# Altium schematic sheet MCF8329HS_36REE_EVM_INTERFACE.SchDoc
size 431 x 279 mm; Date: Not shown in title block; ApprovedBy: Not shown in title block; CheckedBy: Not shown in title block; Author: Not shown in title block; CompanyName: Not shown in title block; Engineer: Not shown in title block; Organization: Not shown in title block; Address1: Not shown in title block; Address2: Not shown in title block; Address3: Not shown in title block; Address4: Not shown in title block; DocumentNumber: 1; Revision: Use project parameter SCH_Rev; SheetNumber: 1; SheetTotal: 5; PageSetup: Record=PageOptions¦CenterHorizontal=True¦CenterVertical=True¦PrintScale=1.00¦XCorrection=1.00¦YCorrection=1.00¦PrintKind=0¦BorderSize=5000000¦LeftOffset=0¦BottomOffset=0¦Orientation=2¦PaperLength=1000¦PaperWidth=1000¦Scale=100¦PaperSource=15¦PrintQuality=600¦MediaType=1¦DitherType=10¦PaperKind=Letter¦PrintScaleMode=1
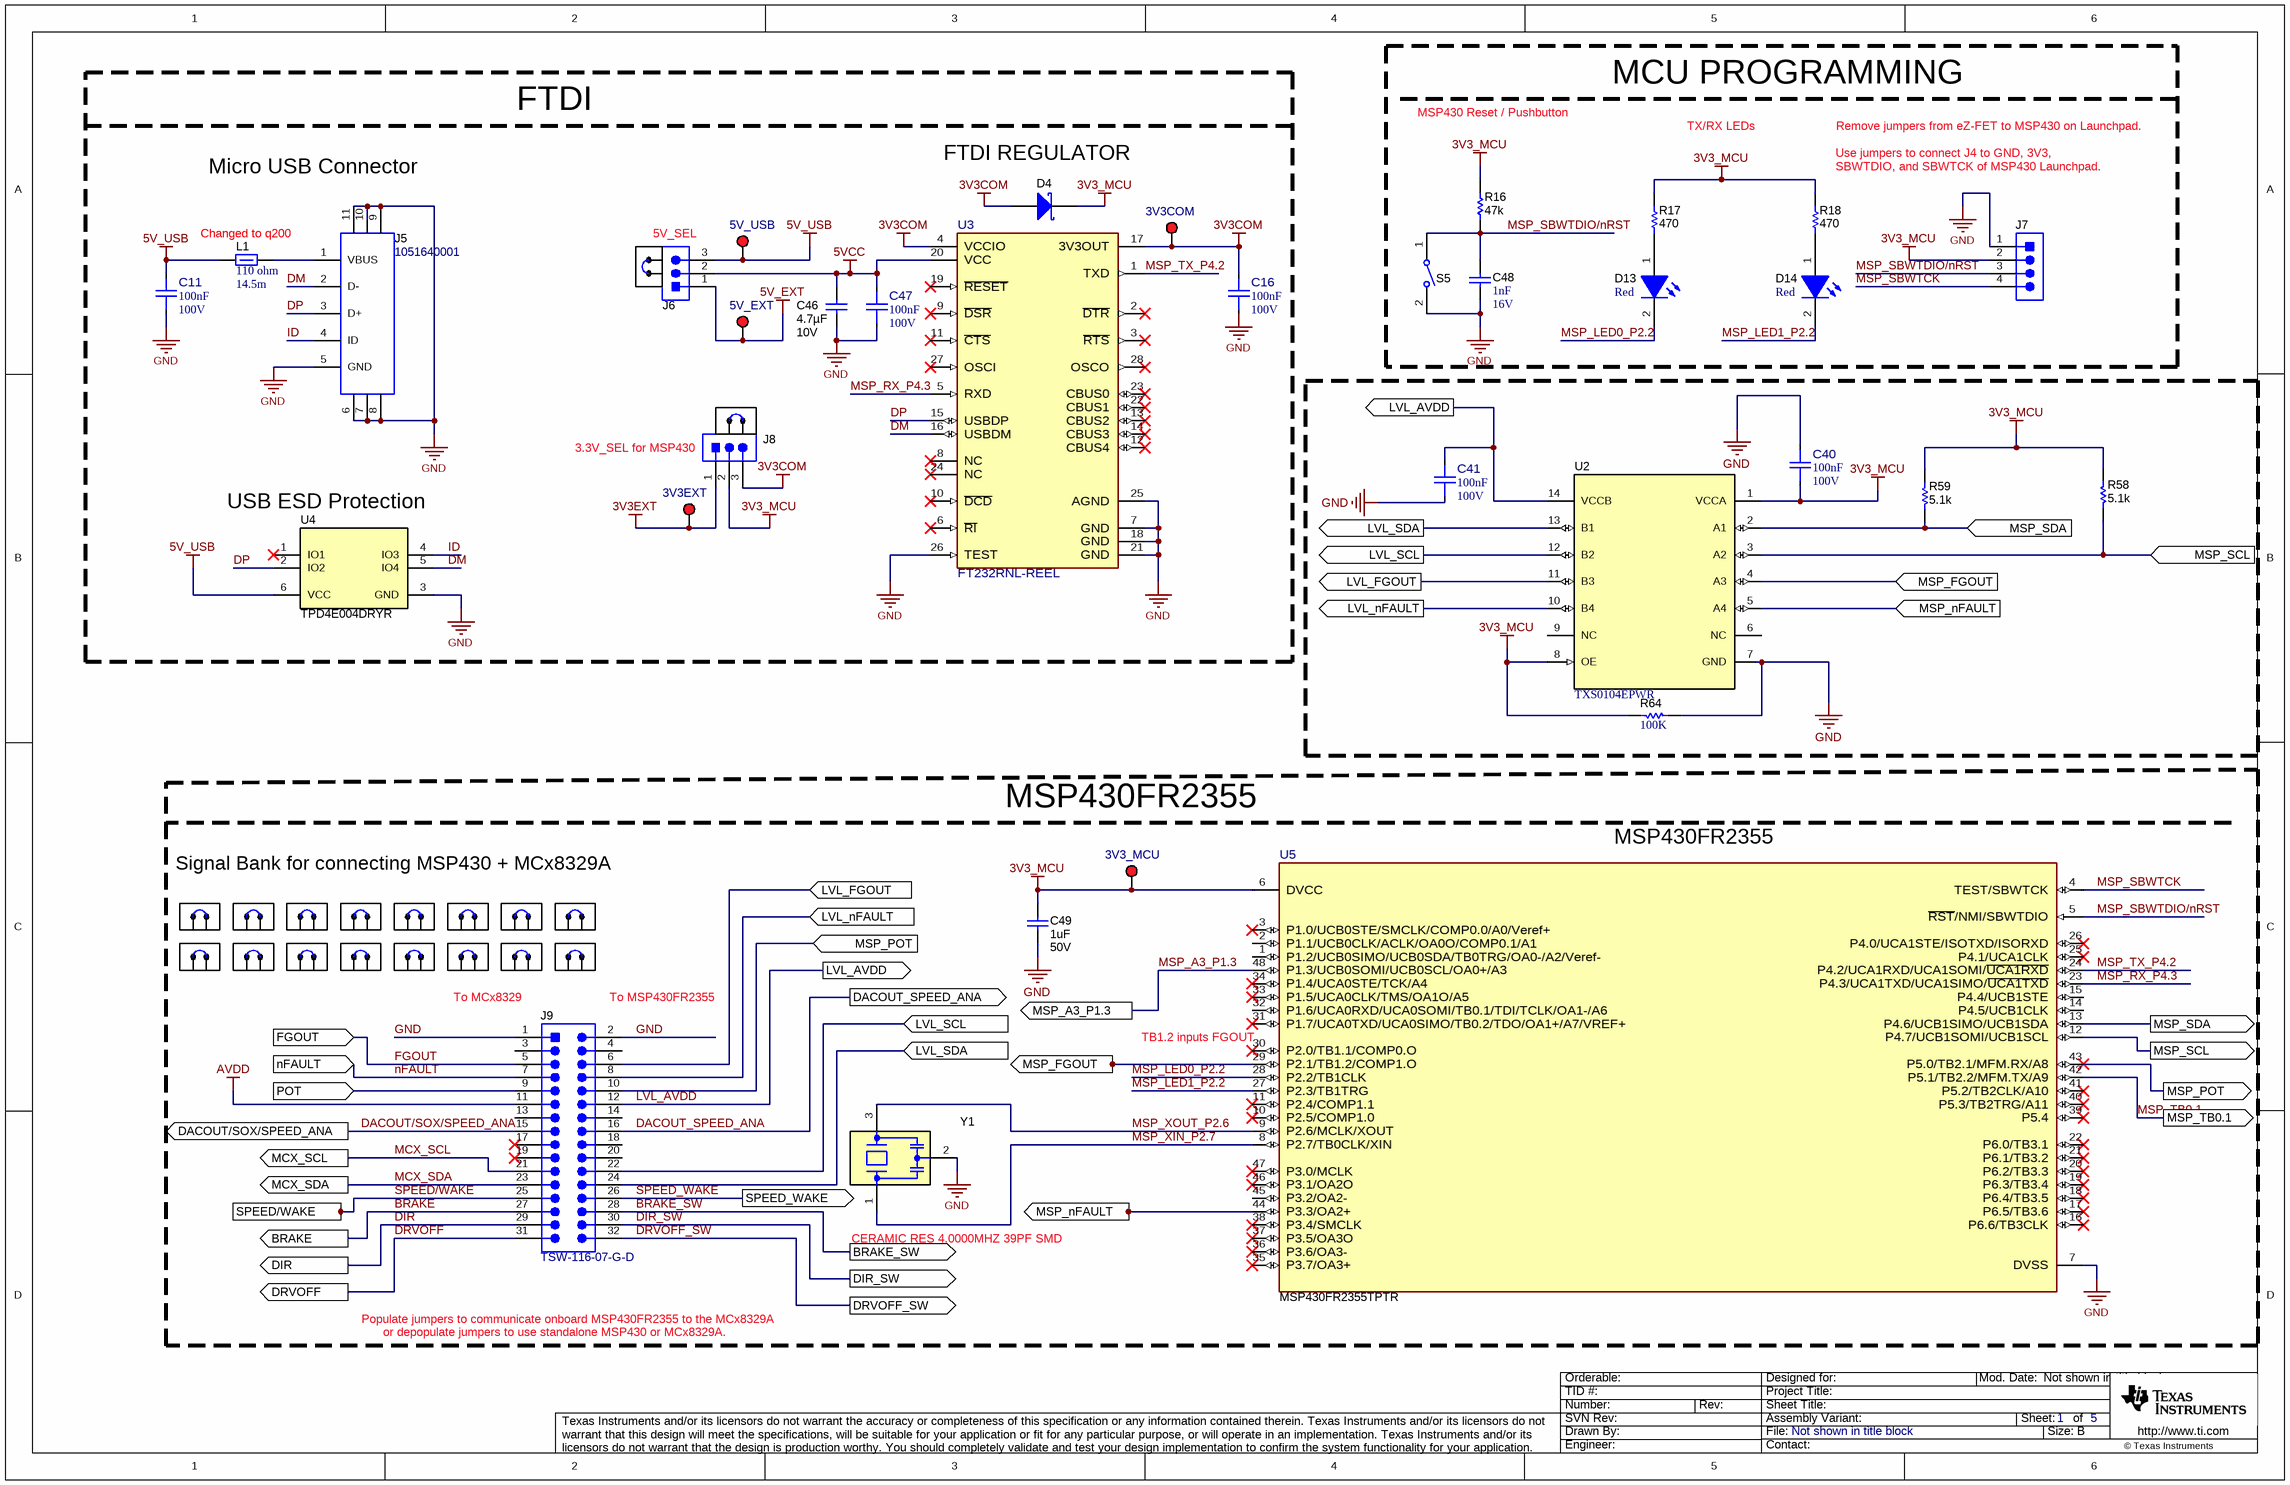
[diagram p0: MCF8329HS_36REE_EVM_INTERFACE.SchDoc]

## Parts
C11  Cap_F: 100nF  VDC_V: 100V  [FP-885012206120_0603-MFG]  (hidden comment: 885012206120)
C16  Cap_F: 100nF  VDC_V: 100V  [FP-885012206120_0603-MFG]  (hidden comment: 885012206120)
C40  Cap_F: 100nF  VDC_V: 100V  [FP-885012206120_0603-MFG]  (hidden comment: 885012206120)
C41  Cap_F: 100nF  VDC_V: 100V  [FP-885012206120_0603-MFG]  (hidden comment: 885012206120)
C46  Cap_F: 4.7µF  VDC_V: 10V  [0603L]  (hidden comment: GRM188Z71A475ME15D)
C47  Cap_F: 100nF  VDC_V: 100V  [FP-885012206120_0603-MFG]  (hidden comment: 885012206120)
C48  Cap_F: 1nF  VDC_V: 16V  [0603L]  (hidden comment: 885012206034)
C49  ValueDisplayed: 1uF  VDC_V: 50V  [0805L]  (hidden comment: 885012207103)
D4  BAT165E6327HTSA1  [SOD-323]  (value not drawn)
D13  Color: Red  [FP-150060RS75003_0603-MFG]  (hidden comment: 150060RS75003)
D14  Color: Red  [FP-150060RS75003_0603-MFG]  (hidden comment: 150060RS75003)
J5  1051640001  [Molex_1051640001]
J6  61300311121  [WURTH_61300311121]  (value not drawn)
J7  61300411121  [WURTH_61300411121]  (value not drawn)
J8  61300311121  [WURTH_61300311121]  (value not drawn)
J9  TSW-116-07-G-D  [TSW-116-07-G-D]
L1  ValueDisplayed: 110 ohm  DCR_ohm: 14.5m  [0603]  (hidden comment: 74279228111)
R16  ValueDisplayed: 47k  [0603L]  (hidden comment: RC0603JR-0747KL)
R17  ValueDisplayed: 470  [0603L]  (hidden comment: RC0603JR-07470RL)
R18  ValueDisplayed: 470  [0603L]  (hidden comment: RC0603JR-07470RL)
R58  ValueDisplayed: 5.1k  [0603L]  (hidden comment: CRCW06035K10JNEA)
R59  ValueDisplayed: 5.1k  [0603L]  (hidden comment: CRCW06035K10JNEA)
R64  ValueDisplayed: 100K  [0603]  (hidden comment: RT0603BRD07100KL)
S5  SW_SPST-single  [SW_434121025816]  (value not drawn)
SH-J4  60900213421  [Wurth_60900213421]  (value not drawn)
SH-J5  60900213421  [Wurth_60900213421]  (value not drawn)
SH-J6  60900213421  [Wurth_60900213421]  (value not drawn)
SH-J10  60900213421  [Wurth_60900213421]  (value not drawn)
SH-J11  60900213421  [Wurth_60900213421]  (value not drawn)
SH-J12  60900213421  [Wurth_60900213421]  (value not drawn)
SH-J13  60900213421  [Wurth_60900213421]  (value not drawn)
SH-J14  60900213421  [Wurth_60900213421]  (value not drawn)
SH-J15  60900213421  [Wurth_60900213421]  (value not drawn)
SH-J16  60900213421  [Wurth_60900213421]  (value not drawn)
SH-J17  60900213421  [Wurth_60900213421]  (value not drawn)
SH-J18  60900213421  [Wurth_60900213421]  (value not drawn)
SH-J19  60900213421  [Wurth_60900213421]  (value not drawn)
SH-J20  60900213421  [Wurth_60900213421]  (value not drawn)
SH-J21  60900213421  [Wurth_60900213421]  (value not drawn)
SH-J22  60900213421  [Wurth_60900213421]  (value not drawn)
SH-J23  60900213421  [Wurth_60900213421]  (value not drawn)
SH-J24  60900213421  [Wurth_60900213421]  (value not drawn)
TP41  3V3COM  [Keystone5000]
TP42  5V_USB  [Keystone5000]
TP43  5V_EXT  [Keystone5000]
TP44  3V3EXT  [Keystone5000]
TP45  3V3_MCU  [Keystone5000]
U2  TXS0104EPWR  [PW0014A_N]
U3  FT232RNL-REEL  [FP-FT232RNL-REEL_SSOP28-MFG]
U4  TPD4E004DRYR  [DRY0006A]
U5  MSP430FR2355TPTR  [PT0048A-MFG]
Y1  CSTCR4M00G55B-R0  [Murata_CSTCR_G]  (value not drawn)

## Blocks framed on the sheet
MCU PROGRAMMING: C48 D13 D14 J7 R16-R18 S5
FTDI: C11 C16 C46 C47 D4 J5 J6 J8 L1 SH-J4 SH-J5 TP41-TP44 U3 U4
MSP430FR2355: C49 J9 SH-J6 SH-J10-SH-J24 TP45 U5 Y1

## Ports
BRAKE (out), BRAKE_SW (out), DACOUT/SOX/SPEED_ANA (out), DACOUT_SPEED_ANA (out), DIR (out), DIR_SW (out), DRVOFF (out), DRVOFF_SW (out), FGOUT (in), LVL_AVDD (out), LVL_FGOUT (in), LVL_FGOUT (out), LVL_nFAULT (in), LVL_nFAULT (out), LVL_SCL (in), LVL_SCL (out), LVL_SDA (in), LVL_SDA (out), MCX_SCL (out), MCX_SDA (out), MSP_A3_P1.3 (out), MSP_FGOUT (in), MSP_FGOUT (out), MSP_nFAULT (in), MSP_nFAULT (out), MSP_POT (in), MSP_POT (out), MSP_SCL (in), MSP_SCL (out), MSP_SDA (in), MSP_SDA (out), MSP_TB0.1 (out), nFAULT (in), POT (in), SPEED/WAKE (out), SPEED_WAKE (out)

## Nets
3V3_MCU: C40.1 C49.1 D4.1(K) J7.2 J8.2 R16.2 R17.2 R18.2 R58.2 R59.2 R64.2 TP45.1 U2.1(VCCA) U2.8(OE) U5.6(DVCC)
3V3COM: C16.2 D4.2(A) J8.3 TP41.1 U3.4(VCCIO) U3.17(3V3OUT)
3V3EXT: J8.1 TP44.1
5V_EXT: J6.1 TP43.1
5V_USB: C11.2 J6.3 L1.1 TP42.1 U4.6(VCC)
5VCC: C46.2 C47.2 J6.2 U3.20(VCC)
AVDD: J9.11
GND: C11.1 C16.1 C40.2 C41.1 C46.1 C47.1 C48.2 C49.2 J5.5(GND) J5.6 J5.7 J5.8 J5.9 J5.10 J5.11 J7.1 J9.1 J9.2 R64.1 S5.2 U2.7(GND) U3.7(GND) U3.18(GND) U3.21(GND) U3.25(AGND) U3.26(TEST) U4.3(GND) U5.7(DVSS) Y1.2(GND)
BRAKE: J9.27 ; port BRAKE
BRAKE_SW: J9.28 ; port BRAKE_SW
DACOUT/SOX/SPEED_ANA: J9.15 ; port DACOUT/SOX/SPEED_ANA
DACOUT_SPEED_ANA: J9.16 ; port DACOUT_SPEED_ANA
DIR: J9.29 ; port DIR
DIR_SW: J9.30 ; port DIR_SW
DM: J5.2(D-) U3.16(USBDM) U4.5(IO4)
DP: J5.3(D+) U3.15(USBDP) U4.2(IO2)
DRVOFF: J9.31 ; port DRVOFF
DRVOFF_SW: J9.32 ; port DRVOFF_SW
FGOUT: J9.5 ; port FGOUT
ID: J5.4(ID) U4.4(IO3)
LVL_AVDD: C41.2 J9.12 U2.14(VCCB) ; port LVL_AVDD
LVL_FGOUT: J9.6 U2.11(B3) ; port LVL_FGOUT
LVL_nFAULT: J9.8 U2.10(B4) ; port LVL_nFAULT
LVL_SCL: J9.22 U2.12(B2) ; port LVL_SCL
LVL_SDA: J9.24 U2.13(B1) ; port LVL_SDA
MCX_SCL: J9.21 ; port MCX_SCL
MCX_SDA: J9.23 ; port MCX_SDA
MSP_A3_P1.3: U5.48(P1.3/UCB0SOMI/UCB0SCL/OA0+/A3) ; port MSP_A3_P1.3
MSP_FGOUT: U2.4(A3) U5.29(P2.1/TB1.2/COMP1.O) ; port MSP_FGOUT
MSP_LED0_P2.2: D13.2(K) U5.28(P2.2/TB1CLK)
MSP_LED1_P2.2: D14.2(K) U5.27(P2.3/TB1TRG)
MSP_nFAULT: U2.5(A4) U5.44(P3.3/OA2+) ; port MSP_nFAULT
MSP_POT: J9.10 U5.43(P5.0/TB2.1/MFM.RX/A8) ; port MSP_POT
MSP_RX_P4.3: U3.5(RXD) U5.23(P4.3/UCA1TXD/UCA1SIMO/~{UCA1TXD})
MSP_SBWTCK: J7.4 U5.4(TEST/SBWTCK)
MSP_SBWTDIO/nRST: C48.1 J7.3 R16.1 S5.1 U5.5(~{RST}/NMI/SBWTDIO)
MSP_SCL: R58.1 U2.3(A2) U5.12(P4.7/UCB1SOMI/UCB1SCL) ; port MSP_SCL
MSP_SDA: R59.1 U2.2(A1) U5.13(P4.6/UCB1SIMO/UCB1SDA) ; port MSP_SDA
MSP_TB0.1: U5.42(P5.1/TB2.2/MFM.TX/A9) ; port MSP_TB0.1
MSP_TX_P4.2: U3.1(TXD) U5.24(P4.2/UCA1RXD/UCA1SOMI/~{UCA1RXD})
MSP_XIN_P2.7: U5.8(P2.7/TB0CLK/XIN) Y1.1(In)
MSP_XOUT_P2.6: U5.9(P2.6/MCLK/XOUT) Y1.3(Out)
nFAULT: J9.7 ; port nFAULT
POT: J9.9 ; port POT
SPEED/WAKE: J9.25 ; port SPEED/WAKE
SPEED_WAKE: J9.26 ; port SPEED_WAKE
NetD13_1: D13.1(A) R17.1
NetD14_1: D14.1(A) R18.1
NetJ5_1: J5.1(VBUS) L1.2

Not connected (* = marked no-connect by the designer): J9 3 4 13 14 17* 18 19* 20; U2 6(NC) 9(NC); U3 2(~{DTR})* 3(~{RTS})* 6(~{RI})* 8(NC)* 9(~{DSR})* 10(~{DCD})* 11(~{CTS})* 12(CBUS4)* 13(CBUS2)* 14(CBUS3)* 19(~{RESET})* 22(CBUS1)* 23(CBUS0)* 24(NC)* 27(OSCI)* 28(OSCO)*; U4 1(IO1)*; U5 1(P1.2/UCB0SIMO/UCB0SDA/TB0TRG/OA0-/A2/Veref-) 2(P1.1/UCB0CLK/ACLK/OA0O/COMP0.1/A1) 3(P1.0/UCB0STE/SMCLK/COMP0.0/A0/Veref+)* 10(P2.5/COMP1.0)* 11(P2.4/COMP1.1)* 14(P4.5/UCB1CLK) 15(P4.4/UCB1STE) 16(P6.6/TB3CLK)* 17(P6.5/TB3.6)* 18(P6.4/TB3.5)* 19(P6.3/TB3.4)* 20(P6.2/TB3.3)* 21(P6.1/TB3.2)* 22(P6.0/TB3.1)* 25(P4.1/UCA1CLK)* 26(P4.0/UCA1STE/ISOTXD/ISORXD)* 30(P2.0/TB1.1/COMP0.O)* 31(P1.7/UCA0TXD/UCA0SIMO/TB0.2/TDO/OA1+/A7/VREF+)* 32(P1.6/UCA0RXD/UCA0SOMI/TB0.1/TDI/TCLK/OA1-/A6) 33(P1.5/UCA0CLK/TMS/OA1O/A5)* 34(P1.4/UCA0STE/TCK/A4)* 35(P3.7/OA3+)* 36(P3.6/OA3-)* 37(P3.5/OA3O)* 38(P3.4/SMCLK)* 39(P5.4)* 40(P5.3/TB2TRG/A11)* 41(P5.2/TB2CLK/A10)* 45(P3.2/OA2-) 46(P3.1/OA2O)* 47(P3.0/MCLK)*

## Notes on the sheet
- Micro USB Connector
- (near D4) FTDI REGULATOR
- MSP430 Reset / Pushbutton
- TX/RX LEDs
- (near R18) Use jumpers to connect J4 to GND, 3V3,
- SBWTDIO, and SBWTCK of MSP430 Launchpad.
- Remove jumpers from eZ-FET to MSP430 on Launchpad.
- (near L1) Changed to q200
- 5V_SEL
- (near U4) USB ESD Protection
- (near J8) 3.3V_SEL for MSP430
- (near U5) MSP430FR2355
- Signal Bank for connecting MSP430 + MCx8329A
- To MCx8329
- To MSP430FR2355
- (near U5) TB1.2 inputs FGOUT
- (near Y1) CERAMIC RES 4.0000MHZ 39PF SMD
- or depopulate jumpers to use standalone MSP430 or MCx8329A.
- Populate jumpers to communicate onboard MSP430FR2355 to the MCx8329A

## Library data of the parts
C11 C16 C40 C41 C47 = CMP-0097294-1: 0.1 µF ±10% 100V Ceramic Capacitor X7R 0603 (1608 Metric); Manufacturer: Wurth Electronics; TempCo: 15%; Value: 100nF; SizeZ_mm: 0.87mm; AEC Qualified: No
C46 = CMP-0007498-4: CAP, CERM, 4.7 uF, 10 V, +/- 20%, X7R, 0603; Manufacturer: MuRata; TaMin_C: -55°C; Polarized: N; SizeAreaWB_mm2: 4.68; Value1: Unknown; U/M: EA; Value: 4.7uF; TaMax_C: 125°C; SizeZ_mm: 1; SizeX_mm: 1.6; SizeY_mm: 0.8; Cap_Case: 0603; SizeArea_mm2: 1.28; AEC Category: Q200
C48 = CMP-0006826-4: CAP, CERM, 1000 pF, 16 V, +/- 10%, X7R, 0603; Manufacturer: Wurth Elektronik; TaMin_C: -55°C; Polarized: N; SizeAreaWB_mm2: 4.68; Value1: Unknown; U/M: EA; Value: 1000pF; TaMax_C: 125°C; SizeZ_mm: 1; SizeX_mm: 1.6; SizeY_mm: 0.8; Cap_Case: 0603; SizeArea_mm2: 1.28; AEC Category: Q200
C49 = CMP-0007696-2: CAP, CERM, 1 uF, 50 V, +/- 10%, X7R, 0805; Manufacturer: Wurth Elektronik; Polarized: N; CompType: Capacitor; Value: 1uF; U/M: EA; Cap_F: 1µF; Value1: Unknown; TaMin_C: -55°C; TaMax_C: 125°C; Cap_Case: 0805; SizeArea_mm2: 2.5; SizeAreaWB_mm2: 6.75; SizeX_mm: 2; SizeY_mm: 1.25; SizeZ_mm: 1.45; AEC Category: Q200
D4 = CMP-0028882-2: Diode, Schottky, 40 V, 0.75 A, AEC-Q101, SOD-323; Manufacturer: Infineon Technologies; Vf_V: 740mV; Value: 40V; Value1: 0.75A; Value2: 0.74V; Io_A: 750mA; TJmax_C: 150°C; AEC Category: Q101; AEC Qualified: Y; Green_Lifecycle: Not Set; Green_REACh: Incomplete; SizeArea_mm2: 3.645; SizeAreaWB_mm2: 8.695; SizeX_mm: 2.7; SizeY_mm: 1.35; SizeZ_mm: 1
D13 D14 = CMP-0121278-2: Red 625nm LED Indication - Discrete 2V 0603 (1608 Metric); Manufacturer: Wurth Electronics; SizeZ_mm: 0.8mm; Angle: 140°; Power_TotalModule: 78mW; LambdaP: 630nm; Tjmax_C: 125°C; Vr_V: 5V; AEC Qualified: No; Forward Current: 20mA; Led Orientation: Top View; Luminous Intensity: 530mcd
J5 = CMP-0055311-1: Receptacle, USB 2.0, Micro B, 5 Position, R/A, SMT; Manufacturer: Molex; CNHeader: FALSE; Current_A: 1.8A; Gender: Female; Voltage_V: 30V; Pitch_mm: 0.65; ContactFinish: Gold; CT: TRUE; Cert_UL: Y
J6 J8 = CMP-0054796-4: Header, 2.54 mm, 3x1, Gold, TH; Manufacturer: Wurth Elektronik; CNHeader: TRUE; CT: FALSE; Green_Lifecycle: Active; Green_REACh: Passed
J7 = CMP-0054798-2: Header, 2.54 mm, 4x1, Gold, TH; Manufacturer: Wurth Elektronik; Pitch_mm: 2.54; Gender: Male; Cert_UL: Y; Shrouded: N; Row_Count: 1
J9 = CMP-0075429-1: Header, 100mil, 16x2, Gold, TH; Manufacturer: Samtec; Pitch_mm: 2.54; Cert_VDE: N; Gender: Male; Cert_CSA: Y; Voltage_V: 550V; Green_REACh: Passed; Current_A: 6.3A; CT: False; Green_Lifecycle: Active; Row_Count: 2; CNHeader: True
L1 = CMP-0003154-2: Ferrite Bead, 110 ohm @ 100 MHz, 4.1 A, 0603; Manufacturer: Wurth Elektronik; SizeX_mm: 1.6; Value: 110 ohm; Value2: 4.1A; Value1: 0.0145 ohm; SizeZ_mm: 1; SizeY_mm: 0.8; SizeAreaWB_mm2: 4.68; SizeArea_mm2: 1.28; Ztyp@1GHz_Ohm: 51.875; ZTyp@100MHz_Ohm: 110
R16 = CMP-0025925-5: RES, 47 k, 5%, 0.1 W, 0603; Manufacturer: Yageo; Power_W: 100mW; TempCo: 100 ppm/C; Value_Code: 47k0; Value: 47k; EIA_Code: E24; SizeX_mm: 1.6; SizeY_mm: 0.8; SizeZ_mm: 1; Value2: 0.1W; SizeArea_mm2: 1.28; AEC Qualified: N; VDC_V: 75V; AEC Category: Q200; SizeAreaWB_mm2: 4.68
R17 R18 = CMP-0025924-5: RES, 470, 5%, 0.1 W, 0603; Manufacturer: Yageo; Power_W: 100mW; TempCo: 100 ppm/C; Value_Code: 470R; Value: 470; EIA_Code: E24; SizeX_mm: 1.6; SizeY_mm: 0.8; SizeZ_mm: 1; Value2: 0.1W; SizeArea_mm2: 1.28; AEC Qualified: N; VDC_V: 75V; AEC Category: Q200; SizeAreaWB_mm2: 4.68
R58 R59 = CMP-0025830-4: RES, 5.1 k, 5%, 0.1 W, AEC-Q200 Grade 0, 0603; Manufacturer: Vishay-Dale; Power_W: 100mW; TempCo: 200 ppm/C; Value_Code: 5k10; Value: 5.1k; EIA_Code: E24; SizeX_mm: 1.6; SizeY_mm: 0.8; SizeZ_mm: 1; Value2: 0.1W; SizeArea_mm2: 1.28; AEC Qualified: Y; VDC_V: 75V; AEC Category: Q200; AEC Grade: 0
R64 = CMP-0023630-3: RES, 100 k, 0.1%, 0.1 W, 0603; Manufacturer: Yageo America; Power_W: 100mW; TempCo: 25 ppm/C; U/M: EA; Value: 100k; EIA_Code: E192; SizeX_mm: 1.6; SizeY_mm: 0.8; SizeZ_mm: 1; Value2: 0.1W; SizeArea_mm2: 1.28; VDC_V: 75V; AEC Category: Q200
S5 = CMP-0002196-2: Switch, Tactile, SPST, 12 V, SMD; PartNumber: 434121025816; Manufacturer: Wurth Elektronik; VDC_V: 12V; SwitchFunction: Off-On; PositionCount: 1; CurrentRating_mA: 50A
SH-J4-SH-J6 SH-J10-SH-J24 = CMP-0003761-2: Shunt, 2.54mm, Gold, Black; Manufacturer: Wurth Elektronik; Value: 1x2
TP41-TP45 = CMP-0055137-1: Test Point, Miniature, Red, TH; PartNumber: 5000; Manufacturer: Keystone; ContactFinish: Silver; CNHeader: FALSE; CT: TRUE; Green_Lifecycle: Active; Green_REACh: Passed
U2 = CMP-0067444-2: 4-Bit Bidirectional Voltage-Level Shifter for Open-Drain and Push-Pull Applications, PW0014A (TSSOP-14); Alternate Manufacturer: Texas Instruments; Green_Lifecycle: Active; SizeAreaWB_mm2: 58.8; Green_REACh: Passed; SizeZ_mm: 1.2; SizeX_mm: 6.4; SizeY_mm: 5.0; SizeArea_mm2: 32.0; CompType: IC; AEC Category: Q200; AEC Qualified: N; Rating: Catalog
U3 = CMP-0121693-1: UART Interface IC USB Full Speed to Serial UART IC, Includes Oscillator and EEPROM, SSOP-28; Manufacturer: FTDI; SizeZ_mm: 2mm; AEC Qualified: No; Data Rate: 3Mbits/s; Interface: UART,USB; Max Supply Voltage: 5.25V; Min Supply Voltage: 1.8V; Nominal Supply Current: 7mA; Number Of Ports: 1; Standoff Height: 0.05mm; TaMax_C: +85°C; TaMin_C: -40°C; Usb Standard: USB 2.0
U4 = CMP-0043115-3: 4-Channel ESD Protection Array for High-Speed Data Interfaces, DRY0006A (USON-6); Manufacturer: Texas Instruments; IO Leakage Current(nA): 1; USB High Speed: TRUE; IO Capacitance(Typ)(pF): 1.6; Eco-Plan: Green (RoHS & no Sb/Br); IEC 61000-4-2 Contact(+/- kV): 8; Breakdown Voltage(Min)(V): 6; IEC 61000-4-2 Air-Gap(+/- kV): 12; AEC Category: Q200; AEC Qualified: N; CompType: IC; SizeAreaWB_mm2: 4.9; SizeArea_mm2: 1.45; SizeX_mm: 1.0; SizeZ_mm: 0.6; Rating: Catalog
U5 = CMP-0089204-1: CPU16 MSP430™ FRAM Microcontroller IC 16-Bit 24MHz 32KB (32K x 8) FRAM 48-LQFP (7x7); Manufacturer: Texas Instruments; Memory Type: OTHER; Data Bus Width: 16bits; Number Of Spi Channels: 4; Number Of I/Os: 44; Number Of Uart Channels: 2; AEC Qualified: No; Standoff Height: 0.05mm; Ram Size: 4KBytes; TaMin_C: -40°C; Core Architecture: RISC; Number Of Adc Channels: 12; SizeZ_mm: 1.6mm; Number Of A/D Converters: 1; Memory Size: 32KBytes; TaMax_C: +105°C; TJmax_C: +115°C; Interface: I2C,SPI,UART,USART,SCI,IrDA; Min Supply Voltage: 1.8V; Max Supply Voltage: 3.6V
Y1 = CMP-0084387-1: Resonator, 4 MHz, 39 pF, AEC-Q200 Grade 1, SMD; Manufacturer: MuRata; Load Capacitance: 39 pF; AEC Qualified: Y; TaMax_C: 125°C; AEC Category: Q200; SizeArea_mm2: 9; SizeZ_mm: 1.2; Frequency_Fixed: 4MHz; SizeAreaWB_mm2: 16.5; SizeY_mm: 2; SizeX_mm: 4.5; TaMin_C: -40°C; AEC Grade: 1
